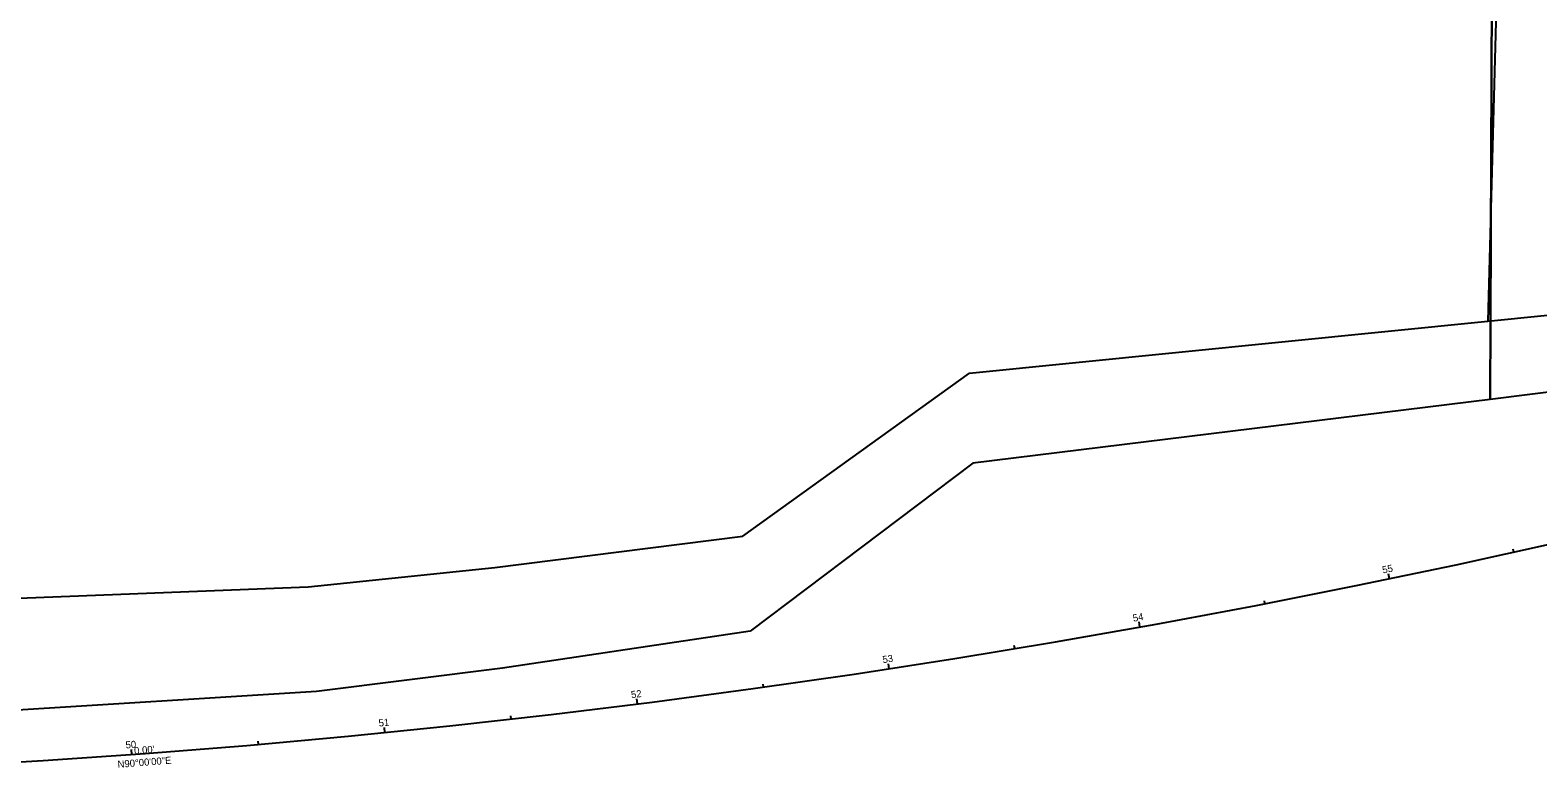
# Model space of a CAD drawing. Extents: x 2272920 to 2277360, y 743591 to 745058.
# Drawn here: x 2275017 to 2275610, y 744214 to 744504 of the extents above; entities that cross this region are included whole.
import ezdxf

# ---------------------------------------------------------------- set-up
doc = ezdxf.new("R2010")
doc.units = 0
for name, color, linetype in [('GE_X_Alignment', 7, 'Continuous'), ('GE_X_Alignment_100_Bearings', 7, 'Continuous'), ('GE_X_Alignment_100_Distances', 7, 'Continuous'), ('GE_X_Alignment_100_Stations', 7, 'Continuous'), ('SC_Scratch1', 7, 'Continuous'), ('SC_Scratch2', 7, 'Continuous')]:
    doc.layers.add(name, color=color, linetype=linetype)

msp = doc.modelspace()

# ---------------------------------------------------------------- linework, layer by layer
at = {"layer": 'GE_X_Alignment'}
msp.add_lwpolyline([(2274981.85, 744214.31), (2275021.89, 744216.67), (2275061.91, 744219.46), (2275101.89, 744222.67), (2275141.84, 744226.3), (2275181.75, 744230.35), (2275221.61, 744234.81), (2275261.43, 744239.7), (2275301.19, 744245), (2275340.89, 744250.72), (2275380.53, 744256.86), (2275420.11, 744263.41), (2275459.61, 744270.38), (2275499.04, 744277.76), (2275538.39, 744285.56), (2275577.65, 744293.77), (2275616.83, 744302.39), (2275655.91, 744311.42), (2275694.9, 744320.86), (2275733.78, 744330.71), (2275772.56, 744340.97), (2275811.23, 744351.63)], dxfattribs=at)
at = {"layer": 'GE_X_Alignment_100_Stations'}
for p, q in [((2275600.37, 744298.77), (2275600.11, 744299.94)), ((2275551.48, 744288.29), (2275551.07, 744290.25)), ((2275502.46, 744278.44), (2275502.23, 744279.62)), ((2275453.31, 744269.27), (2275452.96, 744271.24)), ((2275404.04, 744260.75), (2275403.85, 744261.93)), ((2275354.67, 744252.85), (2275354.37, 744254.83)), ((2275305.2, 744245.58), (2275305.03, 744246.77)), ((2275255.64, 744238.99), (2275255.4, 744240.97)), ((2275205.99, 744233.06), (2275205.86, 744234.26)), ((2275156.28, 744227.76), (2275156.07, 744229.75)), ((2275106.5, 744223.09), (2275106.39, 744224.28)), ((2275056.66, 744219.1), (2275056.52, 744221.09))]:
    msp.add_line(p, q, dxfattribs=at)
at = {"layer": 'SC_Scratch1'}
for p, q in [((2275594.08, 745022.12), (2275591, 744358.88)), ((2275591, 744358.88), (2275594.08, 745022.12)), ((2275800.25, 744384.65), (2275591, 744358.88)), ((2275591, 744358.88), (2275387.55, 744333.82)), ((2275387.55, 744333.82), (2275299.94, 744267.61)), ((2275299.94, 744267.61), (2275202.59, 744253.07)), ((2275202.59, 744253.07), (2275129.35, 744243.83)), ((2275129.35, 744243.83), (2274854.97, 744226.92))]:
    msp.add_line(p, q, dxfattribs=at)
msp.add_lwpolyline([(2274981.85, 744214.31), (2275021.89, 744216.67), (2275061.91, 744219.46), (2275101.89, 744222.67), (2275141.84, 744226.3), (2275181.75, 744230.35), (2275221.61, 744234.81), (2275261.43, 744239.7), (2275301.19, 744245), (2275340.89, 744250.72), (2275380.53, 744256.86), (2275420.11, 744263.41), (2275459.61, 744270.38), (2275499.04, 744277.76), (2275538.39, 744285.56), (2275577.65, 744293.77), (2275616.83, 744302.39), (2275655.91, 744311.42), (2275694.9, 744320.86), (2275733.78, 744330.71), (2275772.56, 744340.97), (2275811.23, 744351.63)], dxfattribs=at)
at = {"layer": 'SC_Scratch2'}
msp.add_lwpolyline([(2274851.36, 744274.32), (2275126.05, 744285.07), (2275199.48, 744292.66), (2275297.13, 744305.01), (2275386.2, 744369.23), (2275590.16, 744389.71), (2275799.94, 744410.77), (2276115.15, 744499.95), (2276183.48, 744528.02), (2276197.17, 745045.41), (2275607.93, 745057.52), (2275590.16, 744389.71)], dxfattribs=at)

# ---------------------------------------------------------------- texts
at = {"layer": 'GE_X_Alignment_100_Bearings'}
msp.add_text('N90°00\'00"E', height=2.8, rotation=4.58797, dxfattribs=at).set_placement((2275051.21, 744213.79))
at = {"layer": 'GE_X_Alignment_100_Distances'}
msp.add_text("0.00'", height=2.8, rotation=4.58797, dxfattribs=at).set_placement((2275057.72, 744219.16))
at = {"layer": 'GE_X_Alignment_100_Stations'}
for s, rotation, p in [('55', 11.80833, (2275548.92, 744290.31)), ('54', 10.00324, (2275450.75, 744271.35)), ('53', 8.79985, (2275352.23, 744255.01)), ('52', 6.99476, (2275253.26, 744241.22)), ('51', 5.79136, (2275153.93, 744230.04)), ('50', 3.98627, (2275054.34, 744221.44))]:
    msp.add_text(s, height=2.8, rotation=rotation, dxfattribs=at).set_placement(p)

doc.saveas('drawing.dxf')
